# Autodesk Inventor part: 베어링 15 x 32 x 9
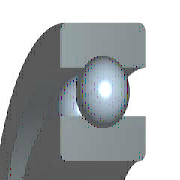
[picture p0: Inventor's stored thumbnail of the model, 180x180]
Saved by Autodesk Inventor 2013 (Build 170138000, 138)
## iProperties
IsCustomPart: 0
Created: 2012-02
Part Number: 베어링 15 x 32 x 9
Material: 강철, 연강
Description: 깊은 그루브 볼 베어링
Document SubType Name: Modeling
Standard: KS B 2023
Designer: mduedu
Standards Organization: KS
Language: ko-KR
Size Designation: 6002 - 15 x 32 x 9
Categories: <MemberInstance><Categories><Category DisplayName="샤프트 부품" InternalName="7f7aeb1f-a693-4053-b835-cee3144e0d98" Mnemonic="SHFT"><Category DisplayName="베어링" Inter
Density: 1 g/cm^3
Author: mduedu
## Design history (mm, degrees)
sketch "스케치" dims "d0" = 4.42 (= -0.26 x WD + 0.26 x BD)
  geometry: L1 (2.29, 11.75)-(6.71, 11.75); L2 (4.5, 11.75)-(4.5, 9.54); L3 (4.5, 11.75)-(4.5, 13.96); L4 (2.858, 10.271)-(0, 10.271); L5 (0, 7.5)-(9, 7.5); L6 (2.858, 13.229)-(0, 13.229); L7 (0, 16)-(9, 16); L8 (9, 7.5)-(9, 10.271); L9 (6.142, 10.271)-(9, 10.271); L10 (6.142, 13.229)-(9, 13.229); L11 (9, 16)-(9, 13.229); L12 (-1.4, 0)-(8.4, 0) reference; L13 (0, -0.3)-(0, 5.3) reference
  constraints: 22 end point, 4 point on line, 2 collinear, 2 perpendicular, 2 symmetric about line, 1 midpoint, 1 parallel, 14 other
  dimensions: "d9" = 15 diameter of L5 L12 (= WD); "d11" = 32 diameter of L7 L12 (= BD); "d12" = 9 distance between parallel lines of L8 L13 (= KB); "d13" = 20.542 diameter of L9 L12 (= 0.326 x BD + 0.674 x WD)
revolve "본체" stored, may be unused: angle "d6" = 90 deg
revolve "볼" stored, may be unused: angle "d7" = 90 deg
pattern_circular "IDS_ARRAYBALL[SIMPL:T]" dims angle "d3" = 360 deg
body "Solid1"
fillet "모깎기1" dims "d1" = 0.3 (= KRS)
other parameters: "WD" = 15 [user parameter; used in 5 equation terms], "BD" = 32 [user parameter; used in 5 equation terms], "KB" = 9 [user parameter; used in 1 equation term], "KRS" = 0.3 [user parameter; used in 1 equation term], "d4" = 0, "d5" = 0, "d8" = 0, "d14" = 0, "d15" = 0, "BBA" = 0 [user parameter], "BC0" = 2850000 [user parameter], "BC" = 5590000 [user parameter], "BR" = 16 (= 0.5 x BD) [user parameter], "WR" = 7.5 (= 0.5 x WD) [user parameter]
